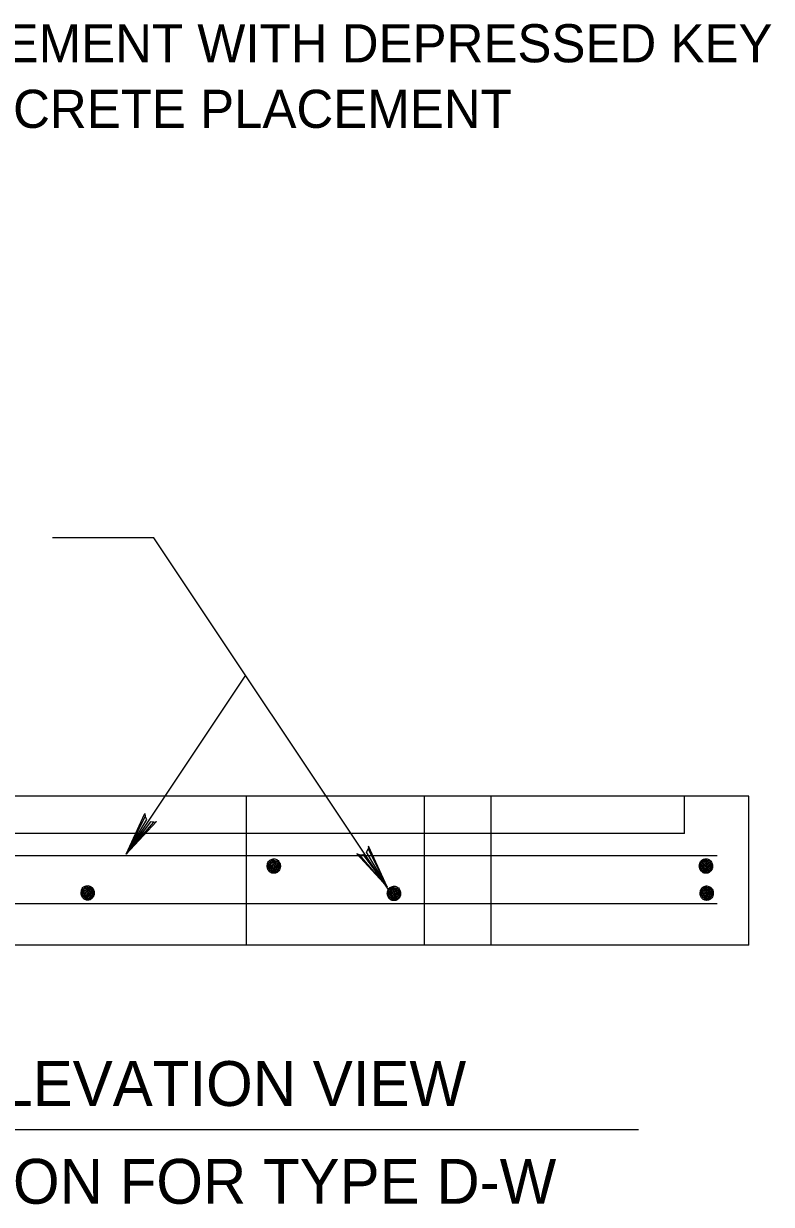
# Model space of a CAD drawing. Extents: x 638877 to 639960, y 297341 to 299123.
# Drawn here: x 639009.8 to 639068.6, y 297559.4 to 297652.3 of the extents above; entities that cross this region are included whole.
import ezdxf

# ---------------------------------------------------------------- set-up
doc = ezdxf.new("R2010")
doc.units = 0
doc.layers.add('2', color=7, linetype='Continuous')
doc.layers.add('3', color=7, linetype='Continuous')

msp = doc.modelspace()

# ---------------------------------------------------------------- linework, layer by layer
at = {"layer": '2'}
for p, q in [((639020.005, 297611.856), (639012.052, 297611.856)), ((639038.49, 297584.121), (639020.005, 297611.856)), ((639027.214, 297601.04), (639017.833, 297586.963)), ((639061.752, 297591.516), (638967.46, 297591.516)), ((639027.318, 297579.816), (639027.318, 297591.516)), ((639041.3, 297579.816), (639041.3, 297591.516)), ((639046.558, 297579.816), (639046.558, 297591.516)), ((639066.822, 297591.516), (639061.752, 297591.516)), ((639061.752, 297588.588), (639061.752, 297591.516)), ((639066.822, 297579.816), (639066.822, 297591.516)), ((639061.752, 297588.588), (638967.46, 297588.588)), ((639064.318, 297586.823), (638965.315, 297586.823)), ((639064.318, 297583.068), (638965.315, 297583.068)), ((639066.822, 297579.816), (638962.396, 297579.816))]:
    msp.add_line(p, q, dxfattribs=at)
for points in [[(639020.012, 297589.485), (639019.744, 297589.514), (639017.833, 297586.963), (639020.012, 297589.485), (639020.225, 297589.545), (639017.833, 297586.963), (639019.466, 297589.696), (639019.333, 297589.925), (639017.833, 297586.963), (639019.299, 297590.161), (639019.333, 297589.925)], [(639036.199, 297586.919), (639036.467, 297586.948), (639038.378, 297584.397), (639036.199, 297586.919), (639035.986, 297586.979), (639038.378, 297584.397), (639036.745, 297587.13), (639036.878, 297587.358), (639038.378, 297584.397), (639036.912, 297587.595), (639036.878, 297587.358)]]:
    msp.add_lwpolyline(points, dxfattribs=at)
for points in [[(639029.447, 297586.025), (639029.503, 297585.991), (639029.499, 297585.942), (639029.413, 297585.939), (639029.372, 297586.017), (639029.413, 297586.111), (639029.499, 297586.107), (639029.548, 297586.055), (639029.555, 297585.942), (639029.503, 297585.871), (639029.417, 297585.834), (639029.308, 297585.89), (639029.286, 297586.002), (639029.319, 297586.137), (639029.394, 297586.208), (639029.525, 297586.201), (639029.608, 297586.133), (639029.634, 297586.017), (639029.615, 297585.913), (639029.566, 297585.826), (639029.484, 297585.785), (639029.379, 297585.763), (639029.278, 297585.793), (639029.211, 297585.894), (639029.184, 297586.051), (639029.248, 297586.22), (639029.357, 297586.306), (639029.503, 297586.306), (639029.626, 297586.249), (639029.712, 297586.133), (639029.72, 297585.942), (639029.652, 297585.811), (639029.536, 297585.729), (639029.413, 297585.684), (639029.271, 297585.703), (639029.166, 297585.811), (639029.106, 297585.969), (639029.143, 297586.216), (639029.267, 297586.369), (639029.439, 297586.403), (639029.608, 297586.369), (639029.739, 297586.268), (639029.787, 297586.122), (639029.783, 297585.894), (639029.686, 297585.718), (639029.555, 297585.632), (639029.409, 297585.609), (639029.286, 297585.628), (639029.147, 297585.68), (639029.05, 297585.826), (639029.027, 297586.062), (639029.076, 297586.272), (639029.207, 297586.425), (639029.364, 297586.489), (639029.559, 297586.47), (639029.742, 297586.403), (639029.825, 297586.287), (639029.888, 297586.077), (639029.862, 297585.864), (639029.798, 297585.707), (639029.682, 297585.594), (639029.551, 297585.534), (639029.413, 297585.534), (639029.271, 297585.538), (639029.132, 297585.579), (639029.05, 297585.654), (639028.982, 297585.77), (639028.949, 297585.89), (639028.926, 297586.002), (639028.952, 297586.156), (639028.994, 297586.306), (639029.08, 297586.437), (639029.196, 297586.527), (639029.334, 297586.571), (639029.469, 297586.594), (639029.615, 297586.56), (639029.739, 297586.5), (639029.847, 297586.396), (639029.922, 297586.268), (639029.963, 297586.133), (639029.971, 297585.98), (639029.933, 297585.804), (639029.847, 297585.654), (639029.761, 297585.561), (639029.649, 297585.486), (639029.529, 297585.46), (639029.357, 297585.46), (639029.308, 297585.463), (639029.177, 297585.534), (639029.072, 297585.628)], [(639063.445, 297586.033), (639063.501, 297585.999), (639063.497, 297585.95), (639063.411, 297585.947), (639063.37, 297586.025), (639063.411, 297586.119), (639063.497, 297586.115), (639063.546, 297586.063), (639063.553, 297585.95), (639063.501, 297585.879), (639063.415, 297585.842), (639063.306, 297585.898), (639063.284, 297586.01), (639063.317, 297586.145), (639063.392, 297586.216), (639063.523, 297586.209), (639063.606, 297586.141), (639063.632, 297586.025), (639063.613, 297585.92), (639063.565, 297585.834), (639063.482, 297585.793), (639063.377, 297585.771), (639063.276, 297585.801), (639063.209, 297585.902), (639063.183, 297586.059), (639063.246, 297586.227), (639063.355, 297586.314), (639063.501, 297586.314), (639063.624, 297586.257), (639063.711, 297586.141), (639063.718, 297585.95), (639063.651, 297585.819), (639063.535, 297585.737), (639063.411, 297585.692), (639063.269, 297585.711), (639063.164, 297585.819), (639063.104, 297585.977), (639063.141, 297586.224), (639063.265, 297586.377), (639063.437, 297586.411), (639063.606, 297586.377), (639063.737, 297586.276), (639063.785, 297586.13), (639063.782, 297585.902), (639063.684, 297585.726), (639063.553, 297585.64), (639063.407, 297585.617), (639063.284, 297585.636), (639063.145, 297585.688), (639063.048, 297585.834), (639063.025, 297586.07), (639063.074, 297586.28), (639063.205, 297586.433), (639063.362, 297586.497), (639063.557, 297586.478), (639063.741, 297586.411), (639063.823, 297586.295), (639063.887, 297586.085), (639063.86, 297585.872), (639063.797, 297585.715), (639063.681, 297585.602), (639063.55, 297585.542), (639063.411, 297585.542), (639063.269, 297585.546), (639063.13, 297585.587), (639063.048, 297585.662), (639062.98, 297585.778), (639062.947, 297585.898), (639062.924, 297586.01), (639062.951, 297586.164), (639062.992, 297586.314), (639063.078, 297586.445), (639063.194, 297586.534), (639063.332, 297586.579), (639063.467, 297586.602), (639063.613, 297586.568), (639063.737, 297586.508), (639063.845, 297586.403), (639063.92, 297586.276), (639063.961, 297586.141), (639063.969, 297585.988), (639063.931, 297585.812), (639063.845, 297585.662), (639063.759, 297585.568), (639063.647, 297585.494), (639063.527, 297585.467), (639063.355, 297585.467), (639063.306, 297585.471), (639063.175, 297585.542), (639063.07, 297585.636)], [(639014.807, 297583.921), (639014.863, 297583.888), (639014.86, 297583.839), (639014.773, 297583.835), (639014.732, 297583.914), (639014.773, 297584.008), (639014.86, 297584.004), (639014.908, 297583.951), (639014.916, 297583.839), (639014.863, 297583.768), (639014.777, 297583.73), (639014.669, 297583.787), (639014.646, 297583.899), (639014.68, 297584.034), (639014.755, 297584.105), (639014.886, 297584.097), (639014.968, 297584.03), (639014.994, 297583.914), (639014.976, 297583.809), (639014.927, 297583.723), (639014.845, 297583.682), (639014.74, 297583.659), (639014.639, 297583.689), (639014.571, 297583.79), (639014.545, 297583.948), (639014.609, 297584.116), (639014.717, 297584.202), (639014.863, 297584.202), (639014.987, 297584.146), (639015.073, 297584.03), (639015.08, 297583.839), (639015.013, 297583.708), (639014.897, 297583.626), (639014.773, 297583.581), (639014.631, 297583.599), (639014.526, 297583.708), (639014.466, 297583.865), (639014.504, 297584.112), (639014.627, 297584.266), (639014.8, 297584.3), (639014.968, 297584.266), (639015.099, 297584.165), (639015.148, 297584.019), (639015.144, 297583.79), (639015.047, 297583.614), (639014.916, 297583.528), (639014.77, 297583.506), (639014.646, 297583.525), (639014.508, 297583.577), (639014.41, 297583.723), (639014.388, 297583.959), (639014.436, 297584.169), (639014.568, 297584.322), (639014.725, 297584.386), (639014.919, 297584.367), (639015.103, 297584.3), (639015.185, 297584.184), (639015.249, 297583.974), (639015.223, 297583.76), (639015.159, 297583.603), (639015.043, 297583.491), (639014.912, 297583.431), (639014.773, 297583.431), (639014.631, 297583.435), (639014.493, 297583.476), (639014.41, 297583.551), (639014.343, 297583.667), (639014.309, 297583.787), (639014.287, 297583.899), (639014.313, 297584.052), (639014.354, 297584.202), (639014.44, 297584.333), (639014.556, 297584.423), (639014.695, 297584.468), (639014.83, 297584.491), (639014.976, 297584.457), (639015.099, 297584.397), (639015.208, 297584.292), (639015.283, 297584.165), (639015.324, 297584.03), (639015.331, 297583.876), (639015.294, 297583.701), (639015.208, 297583.551), (639015.122, 297583.457), (639015.009, 297583.382), (639014.889, 297583.356), (639014.717, 297583.356), (639014.669, 297583.36), (639014.538, 297583.431), (639014.433, 297583.525)], [(639038.902, 297583.877), (639038.959, 297583.844), (639038.955, 297583.795), (639038.869, 297583.791), (639038.828, 297583.87), (639038.869, 297583.964), (639038.955, 297583.96), (639039.003, 297583.907), (639039.011, 297583.795), (639038.959, 297583.724), (639038.872, 297583.687), (639038.764, 297583.743), (639038.741, 297583.855), (639038.775, 297583.99), (639038.85, 297584.061), (639038.981, 297584.053), (639039.063, 297583.986), (639039.09, 297583.87), (639039.071, 297583.765), (639039.022, 297583.679), (639038.94, 297583.638), (639038.835, 297583.615), (639038.734, 297583.645), (639038.667, 297583.746), (639038.64, 297583.904), (639038.704, 297584.072), (639038.813, 297584.158), (639038.959, 297584.158), (639039.082, 297584.102), (639039.168, 297583.986), (639039.176, 297583.795), (639039.108, 297583.664), (639038.992, 297583.582), (639038.869, 297583.537), (639038.726, 297583.555), (639038.622, 297583.664), (639038.562, 297583.821), (639038.599, 297584.068), (639038.723, 297584.222), (639038.895, 297584.256), (639039.063, 297584.222), (639039.194, 297584.121), (639039.243, 297583.975), (639039.239, 297583.746), (639039.142, 297583.57), (639039.011, 297583.484), (639038.865, 297583.462), (639038.741, 297583.481), (639038.603, 297583.533), (639038.506, 297583.679), (639038.483, 297583.915), (639038.532, 297584.125), (639038.663, 297584.278), (639038.82, 297584.342), (639039.015, 297584.323), (639039.198, 297584.256), (639039.281, 297584.14), (639039.344, 297583.93), (639039.318, 297583.716), (639039.254, 297583.559), (639039.138, 297583.447), (639039.007, 297583.387), (639038.869, 297583.387), (639038.726, 297583.391), (639038.588, 297583.432), (639038.506, 297583.507), (639038.438, 297583.623), (639038.404, 297583.743), (639038.382, 297583.855), (639038.408, 297584.009), (639038.449, 297584.158), (639038.535, 297584.289), (639038.652, 297584.379), (639038.79, 297584.424), (639038.925, 297584.447), (639039.071, 297584.413), (639039.194, 297584.353), (639039.303, 297584.248), (639039.378, 297584.121), (639039.419, 297583.986), (639039.427, 297583.833), (639039.389, 297583.657), (639039.303, 297583.507), (639039.217, 297583.413), (639039.105, 297583.338), (639038.985, 297583.312), (639038.813, 297583.312), (639038.764, 297583.316), (639038.633, 297583.387), (639038.528, 297583.481)], [(639063.503, 297583.896), (639063.559, 297583.862), (639063.555, 297583.814), (639063.469, 297583.81), (639063.428, 297583.889), (639063.469, 297583.982), (639063.555, 297583.979), (639063.604, 297583.926), (639063.611, 297583.814), (639063.559, 297583.743), (639063.473, 297583.705), (639063.364, 297583.761), (639063.342, 297583.874), (639063.376, 297584.009), (639063.45, 297584.08), (639063.582, 297584.072), (639063.664, 297584.005), (639063.69, 297583.889), (639063.671, 297583.784), (639063.623, 297583.698), (639063.54, 297583.657), (639063.436, 297583.634), (639063.334, 297583.664), (639063.267, 297583.765), (639063.241, 297583.922), (639063.304, 297584.091), (639063.413, 297584.177), (639063.559, 297584.177), (639063.683, 297584.121), (639063.769, 297584.005), (639063.776, 297583.814), (639063.709, 297583.683), (639063.593, 297583.6), (639063.469, 297583.555), (639063.327, 297583.574), (639063.222, 297583.683), (639063.162, 297583.84), (639063.2, 297584.087), (639063.323, 297584.241), (639063.495, 297584.274), (639063.664, 297584.241), (639063.795, 297584.14), (639063.844, 297583.994), (639063.84, 297583.765), (639063.743, 297583.589), (639063.611, 297583.503), (639063.465, 297583.481), (639063.342, 297583.499), (639063.203, 297583.552), (639063.106, 297583.698), (639063.084, 297583.934), (639063.132, 297584.143), (639063.263, 297584.297), (639063.421, 297584.36), (639063.615, 297584.342), (639063.799, 297584.274), (639063.881, 297584.158), (639063.945, 297583.949), (639063.918, 297583.735), (639063.855, 297583.578), (639063.739, 297583.466), (639063.608, 297583.406), (639063.469, 297583.406), (639063.327, 297583.409), (639063.188, 297583.451), (639063.106, 297583.526), (639063.039, 297583.642), (639063.005, 297583.761), (639062.982, 297583.874), (639063.009, 297584.027), (639063.05, 297584.177), (639063.136, 297584.308), (639063.252, 297584.398), (639063.391, 297584.443), (639063.525, 297584.465), (639063.671, 297584.432), (639063.795, 297584.372), (639063.904, 297584.267), (639063.978, 297584.14), (639064.02, 297584.005), (639064.027, 297583.851), (639063.99, 297583.675), (639063.904, 297583.526), (639063.817, 297583.432), (639063.705, 297583.357), (639063.585, 297583.331), (639063.413, 297583.331), (639063.364, 297583.335), (639063.233, 297583.406), (639063.129, 297583.499)]]:
    msp.add_spline(points, degree=3, dxfattribs=at)
at = {"layer": '3'}
msp.add_line((638985.643, 297565.301), (639058.146, 297565.301), dxfattribs=at)

# ---------------------------------------------------------------- texts
for s, height, p in [('*23" FOR CONCRETE PLACEMENT WITH DEPRESSED KEY', 2.99988, (638956.032, 297649.259)), (' 21" FOR MONOLITHIC CONCRETE PLACEMENT', 2.99988, (638956.032, 297644.099)), ('FRONT ELEVATION VIEW', 3.52986, (638987.145, 297567.152)), ('BASE SECTION FOR TYPE D-W', 3.52986, (638981.128, 297559.461))]:
    msp.add_text(s, height=height, dxfattribs=at).set_placement(p)

doc.saveas('drawing.dxf')
